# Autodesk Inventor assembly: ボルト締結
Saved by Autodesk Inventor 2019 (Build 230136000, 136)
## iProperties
Created: 2018-04
Part Number: ボルト締結
Document SubType Name: Assembly
Designer: shimont
ClientObjectVersion: 1
Author: shimont
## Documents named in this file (1)
- C:\Demo\Inventor_Gate\GateAssy\デザイン アクセラレータ\ボルト締結1.iam
